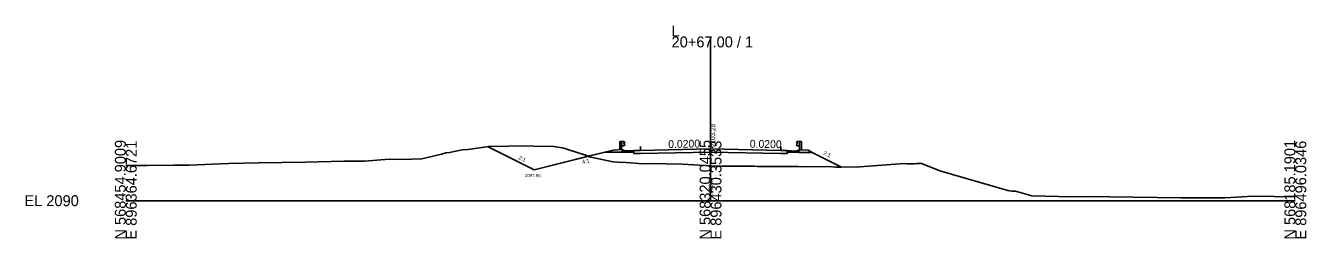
# Model space of a CAD drawing. Extents: x -26 to 1603, y -10 to 13527.
# Drawn here: x 1274.3 to 1602.8, y 990.3 to 1045 of the extents above; entities that cross this region are included whole.
import ezdxf

# ---------------------------------------------------------------- set-up
doc = ezdxf.new("R2010")
doc.units = 0
for name, color, linetype in [('Default', 7, 'Continuous'), ('Exist XS Center Line Elevation Label', 7, 'Continuous'), ('Exist XS Ground Line', 7, 'Continuous'), ('Old_Level_3', 7, 'Continuous'), ('Old_Level_63', 7, 'Continuous'), ('Prop XS Ditch Slope Text', 7, 'Continuous'), ('Prop XS Ditch Standard Text', 7, 'Continuous'), ('Prop XS Dump Level', 7, 'Continuous'), ('Prop XS Earthwork Shape', 7, 'Continuous'), ('Prop XS EOT Tick Mark', 7, 'Continuous'), ('Prop XS Finish Grade', 7, 'Continuous'), ('Prop XS Finish Grade Earthwork', 7, 'Continuous'), ('Prop XS Finish Grade Paved Shoulder', 7, 'Continuous'), ('Prop XS Finish Grade Pavement', 7, 'Continuous'), ('Prop XS Side Slope Text', 7, 'Continuous'), ('Prop XS Subgrade Earthwork', 7, 'Continuous'), ('Prop XSC Text', 7, 'Continuous'), ('Typical Curb CELL', 7, 'Continuous')]:
    doc.layers.add(name, color=color, linetype=linetype)

msp = doc.modelspace()

# ---------------------------------------------------------------- linework, layer by layer
at = {"layer": 'Exist XS Ground Line'}
for p, q in [((1375.96, 1010.75), (1380.98, 1011.98)), ((1375.96, 1010.75), (1380.98, 1011.98)), ((1380.98, 1011.98), (1382.06, 1012.25)), ((1380.98, 1011.98), (1382.06, 1012.25)), ((1382.06, 1012.25), (1383.01, 1012.4)), ((1382.06, 1012.25), (1383.01, 1012.4)), ((1383.01, 1012.4), (1386.28, 1013.06)), ((1383.01, 1012.4), (1386.28, 1013.06)), ((1386.28, 1013.06), (1387.78, 1013.18)), ((1386.28, 1013.06), (1387.78, 1013.18)), ((1387.78, 1013.18), (1393.11, 1013.88)), ((1387.78, 1013.18), (1393.11, 1013.88)), ((1393.11, 1013.88), (1398.3, 1013.99)), ((1393.11, 1013.88), (1398.3, 1013.99)), ((1398.3, 1013.99), (1401.45, 1014.06)), ((1398.3, 1013.99), (1401.45, 1014.06)), ((1401.45, 1014.06), (1404.64, 1014.04)), ((1401.45, 1014.06), (1404.64, 1014.04)), ((1404.64, 1014.04), (1409.74, 1013.95)), ((1404.64, 1014.04), (1409.74, 1013.95)), ((1409.74, 1013.95), (1412, 1013.54)), ((1409.74, 1013.95), (1412, 1013.54)), ((1412, 1013.54), (1412.38, 1013.51)), ((1412, 1013.54), (1412.38, 1013.51)), ((1412.38, 1013.51), (1416.85, 1012.07)), ((1412.38, 1013.51), (1416.85, 1012.07)), ((1416.85, 1012.07), (1417.78, 1011.78)), ((1416.85, 1012.07), (1417.78, 1011.78)), ((1300, 1009.03), (1305.37, 1009.02)), ((1300, 1009.03), (1305.37, 1009.02)), ((1305.37, 1009.02), (1312.31, 1009.08)), ((1305.37, 1009.02), (1312.31, 1009.08)), ((1312.31, 1009.08), (1316.15, 1009.16)), ((1312.31, 1009.08), (1316.15, 1009.16)), ((1316.15, 1009.16), (1326.33, 1009.58)), ((1316.15, 1009.16), (1326.33, 1009.58)), ((1326.33, 1009.58), (1333.98, 1009.69)), ((1326.33, 1009.58), (1333.98, 1009.69)), ((1333.98, 1009.69), (1346.1, 1009.92)), ((1333.98, 1009.69), (1346.1, 1009.92)), ((1346.1, 1009.92), (1355.92, 1010.14)), ((1346.1, 1009.92), (1355.92, 1010.14)), ((1355.92, 1010.14), (1361.21, 1010.12)), ((1355.92, 1010.14), (1361.21, 1010.12)), ((1361.21, 1010.12), (1367.57, 1010.64)), ((1361.21, 1010.12), (1367.57, 1010.64)), ((1367.57, 1010.64), (1369.61, 1010.54)), ((1367.57, 1010.64), (1369.61, 1010.54)), ((1369.61, 1010.54), (1373.39, 1010.63)), ((1369.61, 1010.54), (1373.39, 1010.63)), ((1373.39, 1010.63), (1375.96, 1010.75)), ((1373.39, 1010.63), (1375.96, 1010.75)), ((1417.78, 1011.78), (1418.86, 1011.26)), ((1417.78, 1011.78), (1418.86, 1011.26)), ((1418.86, 1011.26), (1425, 1009.96)), ((1418.86, 1011.26), (1425, 1009.96)), ((1425, 1009.96), (1426.11, 1009.89)), ((1425, 1009.96), (1426.11, 1009.89)), ((1426.11, 1009.89), (1428.36, 1009.77)), ((1426.11, 1009.89), (1428.36, 1009.77)), ((1428.36, 1009.77), (1432.71, 1009.46)), ((1428.36, 1009.77), (1432.71, 1009.46)), ((1432.71, 1009.46), (1434.28, 1009.55)), ((1432.71, 1009.46), (1434.28, 1009.55)), ((1434.28, 1009.55), (1442.79, 1009.38)), ((1434.28, 1009.55), (1442.79, 1009.38)), ((1442.79, 1009.38), (1450, 1008.97)), ((1442.79, 1009.38), (1450, 1008.97)), ((1450, 1008.97), (1451.74, 1008.87)), ((1450, 1008.97), (1451.74, 1008.87)), ((1451.74, 1008.87), (1452.17, 1008.85)), ((1451.74, 1008.87), (1452.17, 1008.85)), ((1452.17, 1008.85), (1461.26, 1008.82)), ((1452.17, 1008.85), (1461.26, 1008.82)), ((1461.26, 1008.82), (1462.02, 1008.81)), ((1461.26, 1008.82), (1462.02, 1008.81)), ((1462.02, 1008.81), (1465.47, 1008.78)), ((1462.02, 1008.81), (1465.47, 1008.78)), ((1465.47, 1008.78), (1472.4, 1008.75)), ((1465.47, 1008.78), (1472.4, 1008.75)), ((1472.4, 1008.75), (1474.29, 1008.72)), ((1472.4, 1008.75), (1474.29, 1008.72)), ((1474.29, 1008.72), (1480.33, 1008.74)), ((1474.29, 1008.72), (1480.33, 1008.74)), ((1480.33, 1008.74), (1482.18, 1008.61)), ((1480.33, 1008.74), (1482.18, 1008.61)), ((1482.18, 1008.61), (1488.32, 1008.73)), ((1482.18, 1008.61), (1488.32, 1008.73)), ((1488.32, 1008.73), (1499.66, 1009.56)), ((1488.32, 1008.73), (1499.66, 1009.56)), ((1499.66, 1009.56), (1500.47, 1009.48)), ((1499.66, 1009.56), (1500.47, 1009.48)), ((1500.47, 1009.48), (1502.26, 1009.5)), ((1500.47, 1009.48), (1502.26, 1009.5)), ((1502.26, 1009.5), (1502.91, 1009.52)), ((1502.26, 1009.5), (1502.91, 1009.52)), ((1502.91, 1009.52), (1503.78, 1009.52)), ((1502.91, 1009.52), (1503.78, 1009.52)), ((1503.78, 1009.52), (1503.91, 1009.65)), ((1503.78, 1009.52), (1503.91, 1009.65)), ((1503.91, 1009.65), (1508.82, 1007.65)), ((1503.91, 1009.65), (1508.82, 1007.65)), ((1508.82, 1007.65), (1526.27, 1002.64)), ((1508.82, 1007.65), (1526.27, 1002.64)), ((1526.27, 1002.64), (1527.29, 1002.48)), ((1526.27, 1002.64), (1527.29, 1002.48)), ((1527.29, 1002.48), (1528.19, 1002.4)), ((1527.29, 1002.48), (1528.19, 1002.4)), ((1528.19, 1002.4), (1532.4, 1001.22)), ((1528.19, 1002.4), (1532.4, 1001.22)), ((1532.4, 1001.22), (1542.66, 1000.95)), ((1532.4, 1001.22), (1542.66, 1000.95)), ((1542.66, 1000.95), (1548.43, 1001.09)), ((1542.66, 1000.95), (1548.43, 1001.09)), ((1548.43, 1001.09), (1552.32, 1000.97)), ((1548.43, 1001.09), (1552.32, 1000.97)), ((1552.32, 1000.97), (1570.65, 1000.77)), ((1552.32, 1000.97), (1570.65, 1000.77)), ((1570.65, 1000.77), (1582.03, 1000.72)), ((1570.65, 1000.77), (1582.03, 1000.72)), ((1582.03, 1000.72), (1589.2, 1001.14)), ((1582.03, 1000.72), (1589.2, 1001.14)), ((1589.2, 1001.14), (1600, 1000.98)), ((1589.2, 1001.14), (1600, 1000.98))]:
    msp.add_line(p, q, dxfattribs=at)
at = {"layer": 'Old_Level_3'}
for p, q in [((1426.69, 1013.11), (1426.69, 1015.22)), ((1426.69, 1015.22), (1427.19, 1015.22)), ((1427.19, 1015.22), (1427.19, 1013.14)), ((1427.19, 1015.22), (1427.69, 1015.22)), ((1427.69, 1015.22), (1427.98, 1015.02)), ((1472.31, 1015.2), (1472.02, 1015)), ((1472.81, 1015.2), (1472.31, 1015.2)), ((1473.31, 1015.2), (1472.81, 1015.2)), ((1472.81, 1015.2), (1472.81, 1013.07)), ((1473.31, 1013.04), (1473.31, 1015.2)), ((1427.69, 1014.08), (1427.19, 1014.08)), ((1427.98, 1014.9), (1427.69, 1014.7)), ((1427.69, 1014.7), (1427.69, 1014.6)), ((1427.69, 1014.6), (1427.98, 1014.4)), ((1427.98, 1014.28), (1427.69, 1014.08)), ((1427.98, 1015.02), (1428.01, 1014.96)), ((1428.01, 1014.96), (1427.98, 1014.9)), ((1427.98, 1014.4), (1428.01, 1014.34)), ((1428.01, 1014.34), (1427.98, 1014.28)), ((1472.02, 1015), (1471.99, 1014.94)), ((1471.99, 1014.94), (1472.02, 1014.88)), ((1472.02, 1014.38), (1471.99, 1014.32)), ((1471.99, 1014.32), (1472.02, 1014.26)), ((1472.02, 1014.88), (1472.31, 1014.68)), ((1472.31, 1014.58), (1472.02, 1014.38)), ((1472.02, 1014.26), (1472.31, 1014.06)), ((1472.31, 1014.68), (1472.31, 1014.58)), ((1472.31, 1014.06), (1472.81, 1014.06))]:
    msp.add_line(p, q, dxfattribs=at)
at = {"layer": 'Old_Level_63'}
for p, q in [((1450, 1000), (1450, 1042.17)), ((1300, 1000), (1450, 1000)), ((1450, 1000), (1600, 1000))]:
    msp.add_line(p, q, dxfattribs=at)
at = {"layer": 'Prop XS Earthwork Shape'}
for points in [[(1392.96, 1013.86), (1393.11, 1013.88), (1398.3, 1013.99), (1401.45, 1014.06), (1404.64, 1014.04), (1409.74, 1013.95), (1412, 1013.54), (1412.38, 1013.51), (1416.85, 1012.07), (1417.78, 1011.78), (1418.57, 1011.4), (1404.78, 1007.96)], [(1468, 1012.13), (1469.66, 1012.1), (1469.66, 1012.47), (1472.68, 1012.4), (1476.08, 1012.4), (1483.61, 1008.64), (1482.18, 1008.61), (1480.33, 1008.74), (1474.29, 1008.72), (1472.4, 1008.75), (1465.47, 1008.78), (1462.02, 1008.81), (1461.26, 1008.82), (1452.17, 1008.85), (1451.74, 1008.87), (1450, 1008.97), (1442.79, 1009.38), (1434.28, 1009.55), (1432.71, 1009.46), (1428.36, 1009.77), (1426.11, 1009.89), (1425, 1009.96), (1418.86, 1011.26), (1418.57, 1011.4), (1422.85, 1012.47), (1427.32, 1012.47), (1430.34, 1012.47), (1430.35, 1012.1), (1432, 1012.13), (1450, 1012.49)]]:
    msp.add_lwpolyline(points, close=True, dxfattribs=at)
at = {"layer": 'Prop XS EOT Tick Mark'}
for p, q in [((1432, 1012.92), (1432, 1013.92)), ((1432, 1012.92), (1432, 1013.92)), ((1432, 1012.92), (1432, 1013.92)), ((1432, 1012.92), (1432, 1013.92)), ((1468, 1012.92), (1468, 1013.92)), ((1468, 1012.92), (1468, 1013.92)), ((1468, 1012.92), (1468, 1013.92))]:
    msp.add_line(p, q, dxfattribs=at)
at = {"layer": 'Prop XS Finish Grade'}
for p, q in [((1425, 1013.01), (1422.85, 1012.47)), ((1427.32, 1013.15), (1425, 1013.01)), ((1428.01, 1012.8), (1427.32, 1013.15)), ((1472.7, 1013.08), (1475, 1012.94)), ((1475, 1012.94), (1476.08, 1012.4))]:
    msp.add_line(p, q, dxfattribs=at)
at = {"layer": 'Prop XS Finish Grade Earthwork'}
for p, q in [((1404.78, 1007.96), (1392.96, 1013.86)), ((1422.85, 1012.47), (1404.78, 1007.96)), ((1476.08, 1012.4), (1483.61, 1008.64))]:
    msp.add_line(p, q, dxfattribs=at)
at = {"layer": 'Prop XS Finish Grade Paved Shoulder'}
for p, q in [((1432, 1012.92), (1430.33, 1012.89)), ((1468, 1012.92), (1469.67, 1012.89))]:
    msp.add_line(p, q, dxfattribs=at)
at = {"layer": 'Prop XS Finish Grade Pavement'}
for p, q in [((1432, 1012.92), (1450, 1013.28)), ((1450, 1013.28), (1468, 1012.92))]:
    msp.add_line(p, q, dxfattribs=at)
at = {"layer": 'Prop XS Subgrade Earthwork'}
for p, q in [((1427.32, 1012.47), (1422.85, 1012.47)), ((1430.34, 1012.47), (1427.32, 1012.47)), ((1430.35, 1012.1), (1430.34, 1012.47)), ((1432, 1012.13), (1430.35, 1012.1)), ((1450, 1012.49), (1432, 1012.13)), ((1468, 1012.13), (1450, 1012.49)), ((1468, 1012.13), (1469.66, 1012.1)), ((1469.66, 1012.47), (1469.66, 1012.1)), ((1472.68, 1012.4), (1469.66, 1012.47)), ((1472.68, 1012.4), (1476.08, 1012.4))]:
    msp.add_line(p, q, dxfattribs=at)
at = {"layer": 'Typical Curb CELL'}
for p, q in [((1427.32, 1012.47), (1427.32, 1013.15)), ((1428.01, 1012.8), (1427.32, 1013.15)), ((1427.32, 1012.47), (1430.34, 1012.47)), ((1427.36, 1012.77), (1427.51, 1012.81)), ((1427.49, 1012.72), (1427.36, 1012.77)), ((1427.51, 1012.81), (1427.49, 1012.72)), ((1428.03, 1012.69), (1427.92, 1012.61)), ((1427.92, 1012.61), (1428.09, 1012.57)), ((1430.33, 1012.89), (1428.01, 1012.8)), ((1428.09, 1012.57), (1428.03, 1012.69)), ((1428.77, 1012.74), (1428.73, 1012.63)), ((1428.73, 1012.63), (1428.85, 1012.62)), ((1428.85, 1012.62), (1428.77, 1012.74)), ((1429.28, 1012.69), (1429.17, 1012.61)), ((1429.17, 1012.61), (1429.34, 1012.57)), ((1429.34, 1012.57), (1429.28, 1012.69)), ((1430.02, 1012.74), (1429.98, 1012.63)), ((1429.98, 1012.63), (1430.1, 1012.62)), ((1430.1, 1012.62), (1430.02, 1012.74)), ((1430.34, 1012.89), (1430.34, 1012.89)), ((1430.34, 1012.47), (1430.34, 1012.88)), ((1469.66, 1012.47), (1469.67, 1012.88)), ((1472.68, 1012.4), (1469.66, 1012.47)), ((1469.67, 1012.89), (1469.67, 1012.89)), ((1469.68, 1012.89), (1472, 1012.75)), ((1469.9, 1012.62), (1469.99, 1012.74)), ((1470.02, 1012.62), (1469.9, 1012.62)), ((1469.99, 1012.74), (1470.02, 1012.62)), ((1470.67, 1012.55), (1470.73, 1012.66)), ((1470.83, 1012.59), (1470.67, 1012.55)), ((1470.73, 1012.66), (1470.83, 1012.59)), ((1471.15, 1012.59), (1471.24, 1012.71)), ((1471.27, 1012.59), (1471.15, 1012.59)), ((1471.24, 1012.71), (1471.27, 1012.59)), ((1471.91, 1012.52), (1471.98, 1012.64)), ((1472.08, 1012.56), (1471.91, 1012.52)), ((1471.98, 1012.64), (1472.08, 1012.56)), ((1472, 1012.75), (1472.7, 1013.08)), ((1472.5, 1012.75), (1472.51, 1012.66)), ((1472.65, 1012.7), (1472.5, 1012.75)), ((1472.51, 1012.66), (1472.65, 1012.7)), ((1472.68, 1012.4), (1472.7, 1013.08))]:
    msp.add_line(p, q, dxfattribs=at)
for centre in [(1427.39, 1012.85), (1427.48, 1012.58), (1427.6, 1012.63), (1427.86, 1012.66), (1427.88, 1012.61), (1428.05, 1012.52), (1428.08, 1012.63), (1428.28, 1012.59), (1428.32, 1012.7), (1428.45, 1012.67), (1428.48, 1012.55), (1428.54, 1012.58), (1428.73, 1012.58), (1428.85, 1012.63), (1428.94, 1012.62), (1429.04, 1012.58), (1429.1, 1012.72), (1429.11, 1012.66), (1429.13, 1012.61), (1429.33, 1012.63), (1429.52, 1012.59), (1429.57, 1012.7), (1429.62, 1012.67), (1429.7, 1012.67), (1429.73, 1012.55), (1429.79, 1012.58), (1429.85, 1012.76), (1430.21, 1012.83), (1430.25, 1012.71), (1469.76, 1012.71), (1469.8, 1012.83), (1470.16, 1012.75), (1470.22, 1012.57), (1470.27, 1012.54), (1470.31, 1012.66), (1470.38, 1012.66), (1470.43, 1012.69), (1470.48, 1012.57), (1470.67, 1012.61), (1470.88, 1012.58), (1470.9, 1012.63), (1470.91, 1012.69), (1470.96, 1012.55), (1471.06, 1012.59), (1471.15, 1012.6), (1471.27, 1012.55), (1471.47, 1012.54), (1471.52, 1012.51), (1471.56, 1012.63), (1471.68, 1012.66), (1471.73, 1012.54), (1471.92, 1012.58), (1471.95, 1012.47), (1472.13, 1012.56), (1472.15, 1012.61), (1472.4, 1012.57), (1472.52, 1012.52), (1472.62, 1012.79)]:
    msp.add_circle(centre, 0.00802, dxfattribs=at)
for centre, start, end in [((1430.33, 1012.88), 0, 92.048), ((1469.68, 1012.88), 86.6704, 178.7184)]:
    msp.add_arc(centre, 0.0104, start, end, dxfattribs=at)

# ---------------------------------------------------------------- texts
at = {"layer": 'Default'}
for rotation, p in [(1.1458, (1439.15, 1013.51)), (358.8597, (1460.05, 1013.63))]:
    msp.add_text('0.0200', height=2, rotation=rotation, dxfattribs=at).set_placement(p)
at = {"layer": 'Exist XS Center Line Elevation Label'}
msp.add_text('2098.97', height=1, rotation=90, dxfattribs=at).set_placement((1450.5, 1001.16))
at = {"layer": 'Old_Level_63'}
for s, p in [('L', (1440, 1042.17)), ('20+67.00 / 1', (1440, 1039.37)), ('EL 2090', (1274, 998.6))]:
    msp.add_text(s, height=2.8, dxfattribs=at).set_placement(p)
for s, p in [('N 568454.9009', (1300, 990)), ('E 896364.6721', (1302.8, 990)), ('N 568320.0455', (1450, 990)), ('E 896430.3533', (1452.8, 990)), ('N 568185.1901', (1600, 990)), ('E 896496.0346', (1602.8, 990))]:
    msp.add_text(s, height=2.8, rotation=90, dxfattribs=at).set_placement(p)
at = {"layer": 'Prop XS Ditch Slope Text'}
msp.add_text('4:1', height=1, rotation=14.0343, dxfattribs=at).set_placement((1417.18, 1009.4))
at = {"layer": 'Prop XS Ditch Standard Text'}
msp.add_text('2097.96', height=0.8, dxfattribs=at).set_placement((1402.43, 1006.04))
at = {"layer": 'Prop XS Dump Level'}
msp.add_text('Case1', height=0.04, dxfattribs=at).set_placement((1472, 1012.57))
at = {"layer": 'Prop XS Side Slope Text'}
for rotation, p in [(333.4443, (1478.83, 1011.93)), (333.4382, (1400.63, 1010.74))]:
    msp.add_text('2:1', height=1, rotation=rotation, dxfattribs=at).set_placement(p)
at = {"layer": 'Prop XSC Text'}
msp.add_text(' 2103.28', height=1.2, rotation=90, dxfattribs=at).set_placement((1451.2, 1013.28))

doc.saveas('drawing.dxf')
